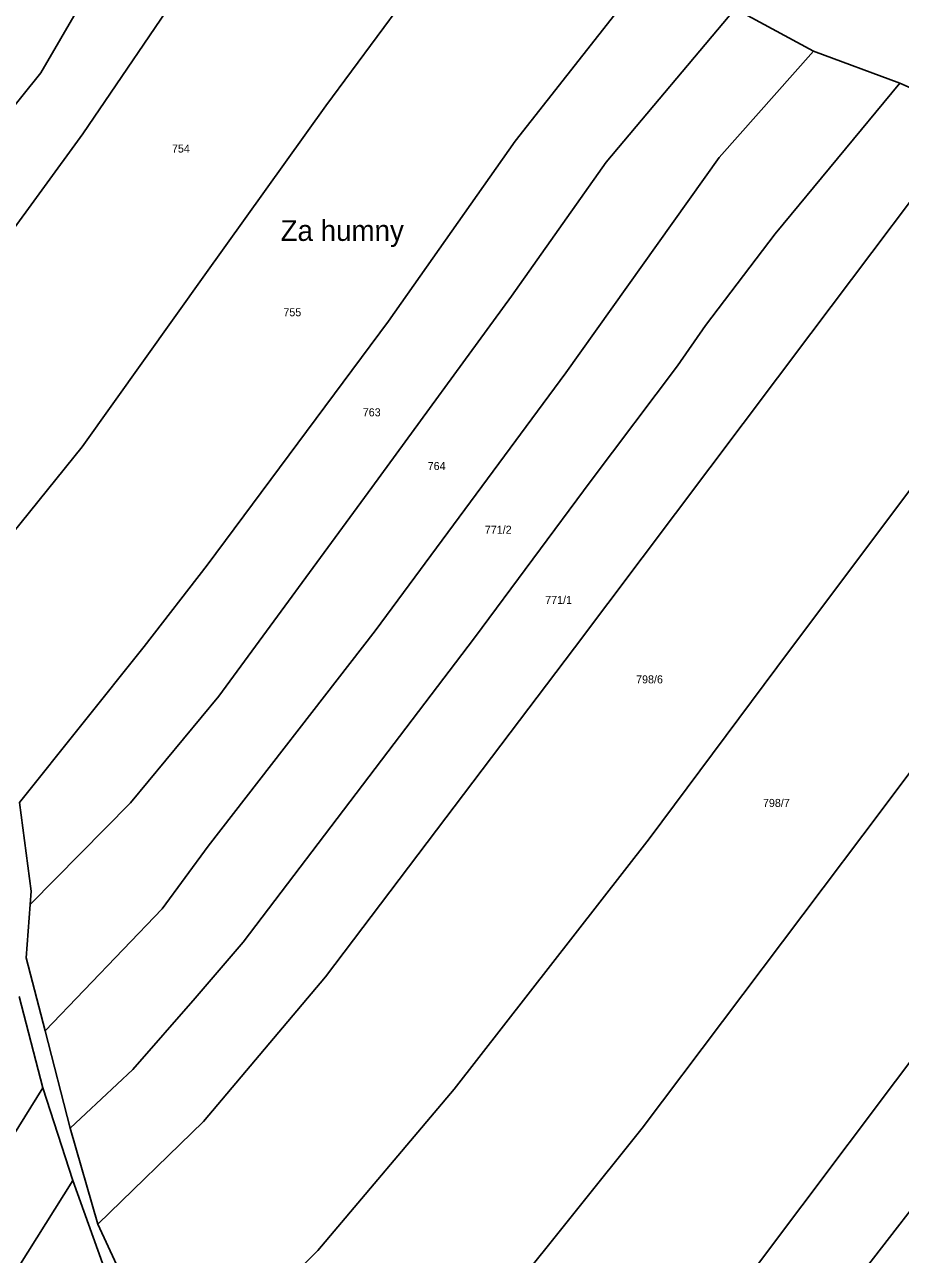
# Model space of a CAD drawing. Extents: x -7476540 to -746055, y -11317203 to -1129777.
# Drawn here: x -748101.7 to -747915.8, y -1131418.4 to -1131157.3 of the extents above; entities that cross this region are included whole.
import ezdxf

# ---------------------------------------------------------------- set-up
doc = ezdxf.new("R2010")
doc.units = 0
for name, color, linetype in [('Hranice parcel', 7, 'Continuous'), ('Parcelní čísla', 7, 'Continuous'), ('Pop  PČ popisy', 7, 'Continuous')]:
    doc.layers.add(name, color=color, linetype=linetype)

msp = doc.modelspace()

# ---------------------------------------------------------------- linework, layer by layer
at = {"layer": 'Hranice parcel'}
for p, q in [((-747950.86, -1131153.99), (-747934.24, -1131162.98)), ((-747934.24, -1131162.98), (-747915.95, -1131169.75)), ((-747915.95, -1131169.75), (-747900.11, -1131176.75)), ((-748102.88, -1131363.67), (-748097.84, -1131383.08)), ((-748092.04, -1131391.66), (-748097.41, -1131370.99)), ((-748097.84, -1131383.08), (-748091.49, -1131402.75)), ((-748086.2, -1131411.99), (-748092.04, -1131391.66)), ((-748091.49, -1131402.75), (-748083.86, -1131424.07)), ((-748069.53, -1131447.82), (-748086.2, -1131411.99))]:
    msp.add_line(p, q, dxfattribs=at)
for points in [[(-748121.21, -1131229.7), (-748114.45, -1131214.85), (-748089.38, -1131180.54), (-748044.49, -1131114.5), (-748028.17, -1131089.42)], [(-748115.5, -1131279.07), (-748089.53, -1131247), (-748063.48, -1131210.43), (-748037.76, -1131174.55), (-748016.02, -1131145.05), (-748011.86, -1131139.28), (-747995.36, -1131116.92)], [(-748078.05, -1131132.75), (-748098.31, -1131167.52), (-748106.65, -1131177.93)], [(-748102.85, -1131322.48), (-748076.38, -1131289.39), (-748063.02, -1131272.11), (-748024.52, -1131220.29), (-747997.58, -1131182.04), (-747965.44, -1131141.16)], [(-748100.59, -1131344.15), (-748079.24, -1131322.55), (-748060.51, -1131299.88), (-748028.05, -1131255.6), (-747998.39, -1131214.99), (-747978.25, -1131186.55), (-747950.86, -1131153.99)], [(-748097.41, -1131370.99), (-748072.55, -1131345.05), (-748062.77, -1131331.73), (-748027.31, -1131286.05), (-747986.85, -1131231.25), (-747954.3, -1131185.56), (-747934.24, -1131162.98)], [(-747915.95, -1131169.75), (-747942.37, -1131201.76), (-747957.17, -1131221.18), (-747963.16, -1131229.8), (-747981.45, -1131254.14), (-748006.25, -1131287.53), (-748028.67, -1131317.02), (-748055.36, -1131352.12), (-748065.51, -1131364.02), (-748078.75, -1131379.21), (-748092.04, -1131391.66)], [(-748086.2, -1131411.99), (-748063.76, -1131390.25), (-748037.84, -1131359.52), (-747984.99, -1131289.67), (-747934.84, -1131222.88), (-747900.11, -1131176.75)], [(-747817.77, -1131191.32), (-747849.87, -1131230.22), (-747870.95, -1131258.84), (-747919.45, -1131323.71), (-747970.67, -1131391.64), (-747999.11, -1131427.19), (-748029.39, -1131463.51), (-748052.97, -1131487.38)], [(-748069.53, -1131447.82), (-748039.5, -1131417.64), (-748010.54, -1131383.33), (-747969.15, -1131330.2), (-747939.35, -1131290.2), (-747874.56, -1131203.77)], [(-748039.41, -1131527.57), (-748021.11, -1131510.35), (-748001.42, -1131490.57), (-747960.37, -1131438.84), (-747946.8, -1131421.49), (-747906.82, -1131368.28), (-747888.73, -1131343.94), (-747857, -1131301.23), (-747832.91, -1131270.59), (-747818.02, -1131250.97), (-747795.27, -1131221.64), (-747787.74, -1131212.45)], [(-748030.59, -1131550.68), (-748006.8, -1131528.34), (-747986.12, -1131504.66), (-747956.18, -1131464.19), (-747938.32, -1131440.9), (-747892.39, -1131381.59), (-747846.71, -1131318.11), (-747774.62, -1131223.12)], [(-748100.59, -1131344.15), (-748100.38, -1131341.3), (-748102.85, -1131322.48)], [(-748097.41, -1131370.99), (-748101.42, -1131355.5), (-748100.59, -1131344.15)], [(-748212.64, -1131547.25), (-748206.7, -1131532.49), (-748202.43, -1131513.11), (-748190.71, -1131502.08), (-748160.01, -1131465.57), (-748146.07, -1131449.57), (-748120.34, -1131419.08), (-748097.84, -1131383.08)], [(-748197.93, -1131550.92), (-748194.08, -1131544.52), (-748189.38, -1131534.76), (-748180.26, -1131514.82), (-748142.13, -1131473.68), (-748122.88, -1131448.54), (-748104.89, -1131424.02), (-748091.49, -1131402.75)]]:
    msp.add_lwpolyline(points, dxfattribs=at)

# ---------------------------------------------------------------- texts
at = {"layer": 'Parcelní čísla'}
for s, p in [('754', (-748070.46, -1131184.48)), ('755', (-748046.8, -1131219.24)), ('763', (-748029.95, -1131240.48)), ('764', (-748016.17, -1131251.89)), ('771/2', (-748004.04, -1131265.42)), ('771/1', (-747991.22, -1131280.33)), ('798/6', (-747971.92, -1131297.19)), ('798/7', (-747944.99, -1131323.43))]:
    msp.add_text(s, height=1.7, dxfattribs=at).set_placement(p)
at = {"layer": 'Pop  PČ popisy'}
msp.add_text('Za humny', height=4.4, dxfattribs=at).set_placement((-748047.39, -1131203.24))

doc.saveas('drawing.dxf')
